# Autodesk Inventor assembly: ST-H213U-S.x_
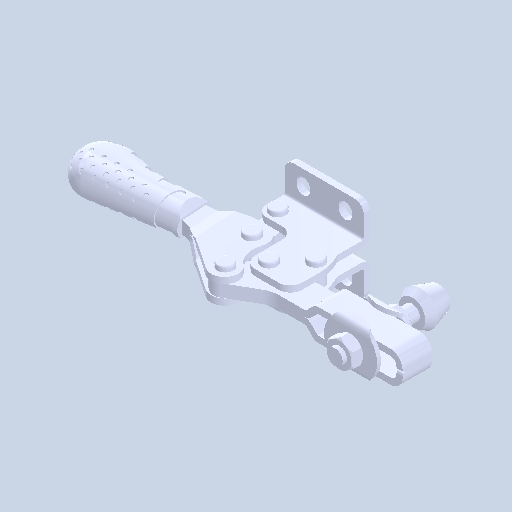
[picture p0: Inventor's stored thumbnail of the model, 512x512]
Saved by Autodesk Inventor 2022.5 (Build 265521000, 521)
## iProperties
Created: 2024-07
Part Number: ST-H213U-S.x_
Document SubType Name: Assembly
Designer: ImaoCorp
Author: ImaoCorp
Sending System: SOLIDWORKS 2022-2022290
MC: AMD64
MC_MODEL: Intel64 Family 6 Model 60 Stepping 3, GenuineIntel
OS: Windows_NT
FRU: Parasolid Version 33.1, build 260,  4-25-2022
FORMAT: text
GUISE: transmit
KEY: FILEST-H213U-S.x_t
DATE: Mon Jul 29 10:01:57 2024
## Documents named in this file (8)
- X:\14_SW2022-Inv2022\07_2024-10新製品(WHS)\OTC_データ\s\st-h213u-s\ST-H213U-S.x_.iam
- X:\14_SW2022-Inv2022\07_2024-10新製品(WHS)\OTC_データ\s\st-h213u-s\ST-H213U-S_01.ipt
- X:\14_SW2022-Inv2022\07_2024-10新製品(WHS)\OTC_データ\s\st-h213u-s\ST-H213U-S_02.ipt
- X:\14_SW2022-Inv2022\07_2024-10新製品(WHS)\OTC_データ\s\st-h213u-s\ST-H213U-S_03.ipt
- X:\14_SW2022-Inv2022\07_2024-10新製品(WHS)\OTC_データ\s\st-h213u-s\ST-H213U-S_04.ipt
- X:\14_SW2022-Inv2022\07_2024-10新製品(WHS)\OTC_データ\s\st-h213u-s\ST-H213U-S_05.ipt
- X:\14_SW2022-Inv2022\07_2024-10新製品(WHS)\OTC_データ\s\st-h213u-s\ST-H213U-S_06.ipt
- X:\14_SW2022-Inv2022\07_2024-10新製品(WHS)\OTC_データ\s\st-h213u-s\ST-H213U-S_07.ipt
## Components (7 placed, 7 different names)
1. ST-H213U-S_01
2. ST-H213U-S_02
3. ST-H213U-S_03
4. ST-H213U-S_04
5. ST-H213U-S_05
6. ST-H213U-S_06
7. ST-H213U-S_07
